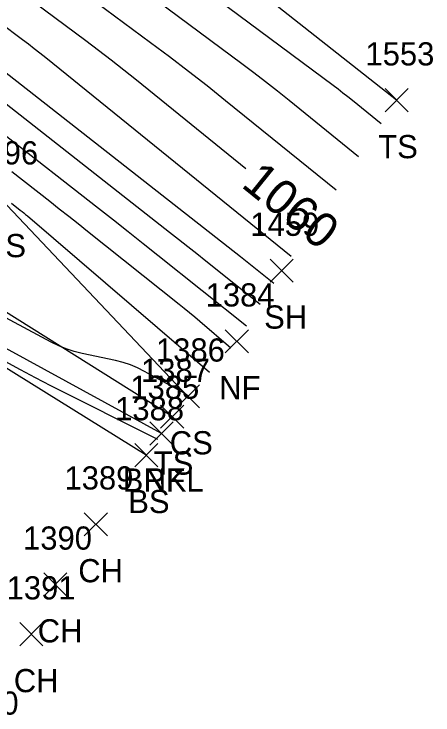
# Model space of a CAD drawing. Extents: x 1592612 to 1596497, y 111838 to 113741.
# Drawn here: x 1592989.2 to 1593025.4, y 113245.6 to 113306.1 of the extents above; entities that cross this region are included whole.
import ezdxf

# ---------------------------------------------------------------- set-up
doc = ezdxf.new("R2010")
doc.units = 0
for name, color, linetype in [('L_A', 7, 'Continuous'), ('L_I', 7, 'Continuous'), ('L_TIC', 7, 'Continuous'), ('LAWE', 7, 'Continuous'), ('LELB', 7, 'Continuous'), ('LSOGCMA', 7, 'Continuous'), ('LSOGCMA_T', 7, 'Continuous'), ('LSOGCMI', 7, 'Continuous')]:
    doc.layers.add(name, color=color, linetype=linetype)

msp = doc.modelspace()

# ---------------------------------------------------------------- linework, layer by layer
at = {"layer": 'L_TIC'}
for points in [[(1593021.223, 113297.621), (1593023.223, 113299.621)], [(1593023.223, 113297.621), (1593021.223, 113299.621)], [(1593011.291, 113282.925), (1593013.291, 113284.925)], [(1593013.291, 113282.925), (1593011.291, 113284.925)], [(1593007.424, 113276.832), (1593009.424, 113278.832)], [(1593009.424, 113276.832), (1593007.424, 113278.832)], [(1593003.188, 113272.082), (1593005.188, 113274.082)], [(1593005.188, 113272.082), (1593003.188, 113274.082)], [(1593001.844, 113270.334), (1593003.844, 113272.334)], [(1593003.844, 113270.334), (1593001.844, 113272.334)], [(1593000.92, 113268.875), (1593002.92, 113270.875)], [(1593002.92, 113268.875), (1593000.92, 113270.875)], [(1593000.92, 113268.875), (1593002.92, 113270.875)], [(1593002.92, 113268.875), (1593000.92, 113270.875)], [(1592999.607, 113267.02), (1593001.607, 113269.02)], [(1593001.607, 113267.02), (1592999.607, 113269.02)], [(1592995.242, 113261.05), (1592997.242, 113263.05)], [(1592997.242, 113261.05), (1592995.242, 113263.05)], [(1592991.744, 113255.864), (1592993.744, 113257.864)], [(1592993.744, 113255.864), (1592991.744, 113257.864)], [(1592989.675, 113251.571), (1592991.675, 113253.571)], [(1592991.675, 113251.571), (1592989.675, 113253.571)]]:
    msp.add_lwpolyline(points, dxfattribs=at)
at = {"layer": 'LAWE'}
msp.add_lwpolyline([(1593001.92, 113269.875), (1592980.168, 113281.757), (1592972.077, 113292.77), (1592952.739, 113309.006), (1592930.405, 113333.014), (1592916.015, 113354.051), (1592913.1, 113363.091), (1592910.596, 113379.281), (1592906.825, 113388.644), (1592902.208, 113400.349), (1592897.68, 113413.914), (1592895.157, 113422.89), (1592891.073, 113425.248), (1592889.456, 113425.542), (1592888.74, 113438.019), (1592887.745, 113444.76), (1592887.496, 113453.354)], dxfattribs=at)
at = {"layer": 'LELB'}
for points in [[(1593000.607, 113268.02), (1592979.237, 113281.269), (1592969.817, 113290.666), (1592952.505, 113308.706), (1592930.32, 113332.83), (1592915.558, 113354.032), (1592906.593, 113378.229), (1592901.651, 113400.349), (1592897.345, 113413.71), (1592894.471, 113422.658), (1592891.543, 113424.972)], [(1593022.223, 113298.621), (1592996.05, 113319.251), (1592973.737, 113329.884), (1592951.567, 113338.734), (1592939.58, 113363.449), (1592930.763, 113371.375), (1592929.879, 113381.446), (1592924.735, 113386.602), (1592927.418, 113411.322), (1592932.961, 113414.131), (1592945.073, 113412.416), (1592963.598, 113404.825), (1592977.398, 113399.854), (1592996.446, 113393.062), (1593007.402, 113387.97)], [(1593002.844, 113271.334), (1592982.233, 113284.253), (1592973.366, 113294.033), (1592954.604, 113311.113), (1592933.333, 113334.792), (1592919.468, 113354.266), (1592918.171, 113363.34), (1592916.481, 113374.12), (1592914.915, 113386.717)], [(1593004.187, 113273.082), (1592988.064, 113290.085), (1592974.924, 113296.668)]]:
    msp.add_lwpolyline(points, dxfattribs=at)
at = {"layer": 'LSOGCMA'}
for points in [[(1592990.937, 113307.069), (1592995.379, 113303.772), (1592996.485, 113302.942), (1592997.583, 113302.1), (1592998.672, 113301.248), (1592999.751, 113300.383), (1593009.211, 113292.732)], [(1593007.899, 113277.243), (1593005.234, 113279.526), (1593004.788, 113279.904), (1593004.339, 113280.279), (1593003.887, 113280.649), (1593003.431, 113281.015), (1592995.538, 113287.301), (1592994.723, 113287.949), (1592993.906, 113288.596), (1592993.087, 113289.24), (1592992.267, 113289.883), (1592988.984, 113292.45)]]:
    msp.add_lwpolyline(points, dxfattribs=at)
at = {"layer": 'LSOGCMI'}
for points in [[(1592963.205, 113317.294), (1592984.839, 113303.675), (1592984.897, 113303.639), (1592984.956, 113303.605), (1592985.016, 113303.572), (1592985.076, 113303.54), (1592985.318, 113303.416), (1592985.378, 113303.384), (1592985.436, 113303.349), (1592985.492, 113303.311), (1592985.547, 113303.27), (1593008.745, 113285.131), (1593009.033, 113284.905), (1593009.32, 113284.679), (1593009.608, 113284.452), (1593009.894, 113284.224), (1593011.612, 113282.856)], [(1592996.762, 113314.741), (1593016.746, 113299.908), (1593017.168, 113299.592), (1593017.586, 113299.271), (1593018.001, 113298.946), (1593018.413, 113298.616), (1593020.874, 113296.626)], [(1593010.438, 113281.005), (1593005.747, 113284.741), (1593004.965, 113285.363), (1593004.181, 113285.983), (1593003.396, 113286.601), (1593002.609, 113287.218), (1592986.852, 113299.539), (1592986.456, 113299.833), (1592986.049, 113300.107), (1592985.628, 113300.362), (1592985.195, 113300.596), (1592983.436, 113301.495), (1592982.999, 113301.725), (1592982.568, 113301.964), (1592982.142, 113302.212), (1592981.721, 113302.47), (1592967.256, 113311.577)], [(1593018.933, 113293.754), (1593012.93, 113298.609), (1593011.925, 113299.413), (1593010.912, 113300.206), (1593009.891, 113300.989), (1593008.862, 113301.761), (1592997.022, 113310.549)], [(1592966.172, 113309.106), (1592966.855, 113308.673), (1592968.331, 113307.738), (1592969.808, 113306.804), (1592971.286, 113305.873), (1592978.603, 113301.266), (1592979.386, 113300.786), (1592980.18, 113300.323), (1592980.983, 113299.877), (1592981.796, 113299.45), (1592985.071, 113297.777), (1592985.878, 113297.34), (1592986.661, 113296.866), (1592987.421, 113296.355), (1592988.157, 113295.808), (1592996.474, 113289.304), (1592997.759, 113288.297), (1592999.042, 113287.287), (1593000.322, 113286.274), (1593001.601, 113285.258), (1593009.264, 113279.155)], [(1592993.98, 113308.809), (1593000.979, 113303.614), (1593002.615, 113302.386), (1593004.239, 113301.142), (1593005.849, 113299.88), (1593007.447, 113298.602), (1593016.992, 113290.881)], [(1593013.11, 113285.137), (1592991.918, 113302.277), (1592991.425, 113302.671), (1592990.928, 113303.06), (1592990.427, 113303.445), (1592989.922, 113303.824), (1592987.894, 113305.329), (1592987.39, 113305.709), (1592986.891, 113306.096)], [(1592988.968, 113289.749), (1592989.717, 113289.152), (1592989.874, 113289.026), (1592990.03, 113288.898), (1592990.185, 113288.769), (1592990.339, 113288.638), (1593006.053, 113275.174)], [(1593004.208, 113273.104), (1593004.04, 113273.249), (1593004.011, 113273.272), (1593003.982, 113273.293), (1593003.951, 113273.314), (1593003.919, 113273.332), (1593000.442, 113275.234), (1592999.843, 113275.534), (1592999.228, 113275.789), (1592998.595, 113275.999), (1592997.946, 113276.163), (1592995.065, 113276.785), (1592994.374, 113276.959), (1592993.7, 113277.179), (1592993.043, 113277.445), (1592992.403, 113277.758), (1592989.211, 113279.453), (1592988.468, 113279.846)], [(1592988.401, 113276.124), (1592989.702, 113275.406), (1592991.014, 113274.709), (1592992.338, 113274.033), (1593001.586, 113269.403)]]:
    msp.add_lwpolyline(points, dxfattribs=at)

# ---------------------------------------------------------------- texts
at = {"layer": 'L_A'}
for s, p in [('TS', (1593020.632, 113293.621)), ('CS', (1592986.505, 113285.085)), ('SH', (1593010.779, 113278.925)), ('NF', (1593006.905, 113272.832)), ('CS', (1593002.629, 113268.082)), ('TS', (1593001.253, 113266.334)), ('BRKL', (1592998.565, 113264.875)), ('NF', (1593000.4, 113264.875)), ('BS', (1592999.048, 113263.02)), ('CH', (1592994.73, 113257.05)), ('CH', (1592991.232, 113251.864)), ('CH', (1592989.163, 113247.571))]:
    msp.add_text(s, height=2, dxfattribs=at).set_placement(p)
at = {"layer": 'L_I'}
for s, p in [('1553', (1593019.53, 113301.621)), ('1396', (1592985.316, 113293.085)), ('1459', (1593009.59, 113286.925)), ('1384', (1593005.731, 113280.832)), ('1386', (1593001.44, 113276.082)), ('1387', (1593000.151, 113274.334)), ('1385', (1592999.227, 113272.875)), ('1385', (1592999.227, 113272.875)), ('1388', (1592997.914, 113271.02)), ('1389', (1592993.541, 113265.05)), ('1390', (1592989.964, 113259.864)), ('1391', (1592988.549, 113255.571)), ('1330', (1592983.629, 113245.634))]:
    msp.add_text(s, height=2, dxfattribs=at).set_placement(p)
at = {"layer": 'LSOGCMA_T'}
msp.add_text('1060', height=3, rotation=321.0347, dxfattribs=at).set_placement((1593008.709, 113291.21))

doc.saveas('drawing.dxf')
